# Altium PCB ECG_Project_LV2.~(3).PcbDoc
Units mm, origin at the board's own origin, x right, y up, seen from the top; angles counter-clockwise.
Board outline 76.71 x 49.78 mm, 2 copper layers (Top Layer, Bottom Layer); 26 components, 19 nets, 74 pads, 0 vias.
Unrouted connection lines stored in the file: 2.
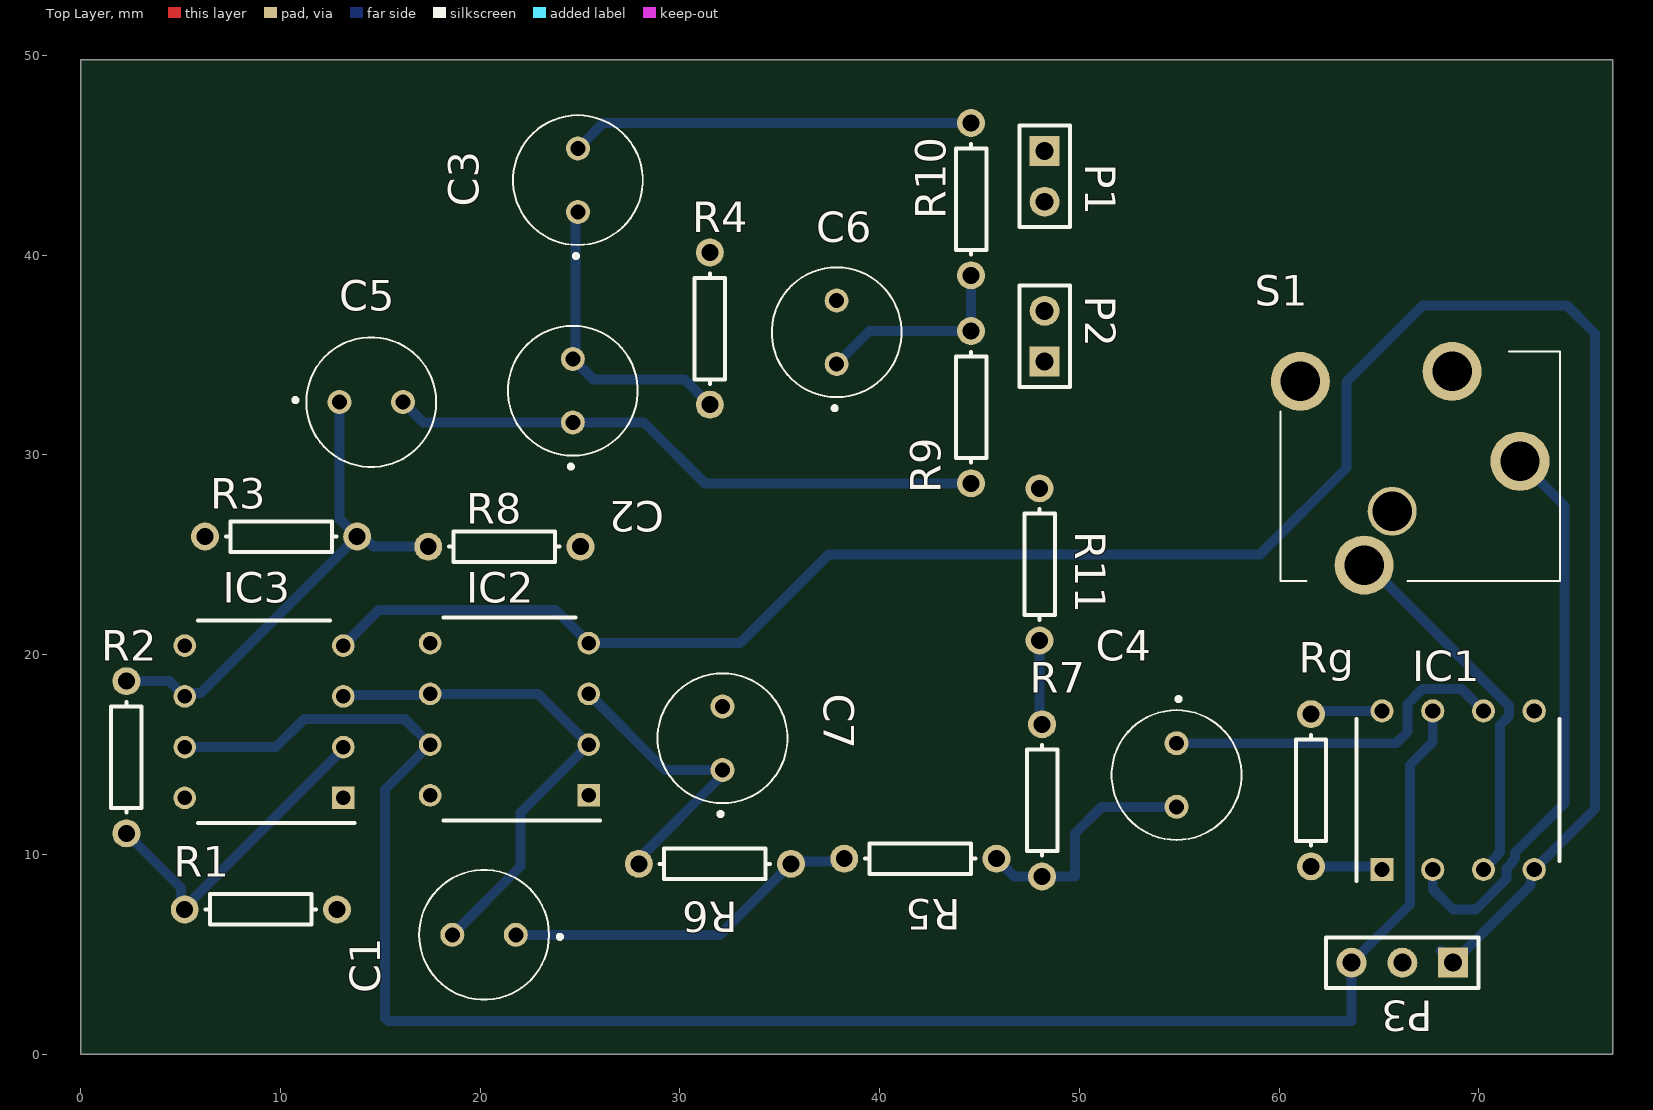
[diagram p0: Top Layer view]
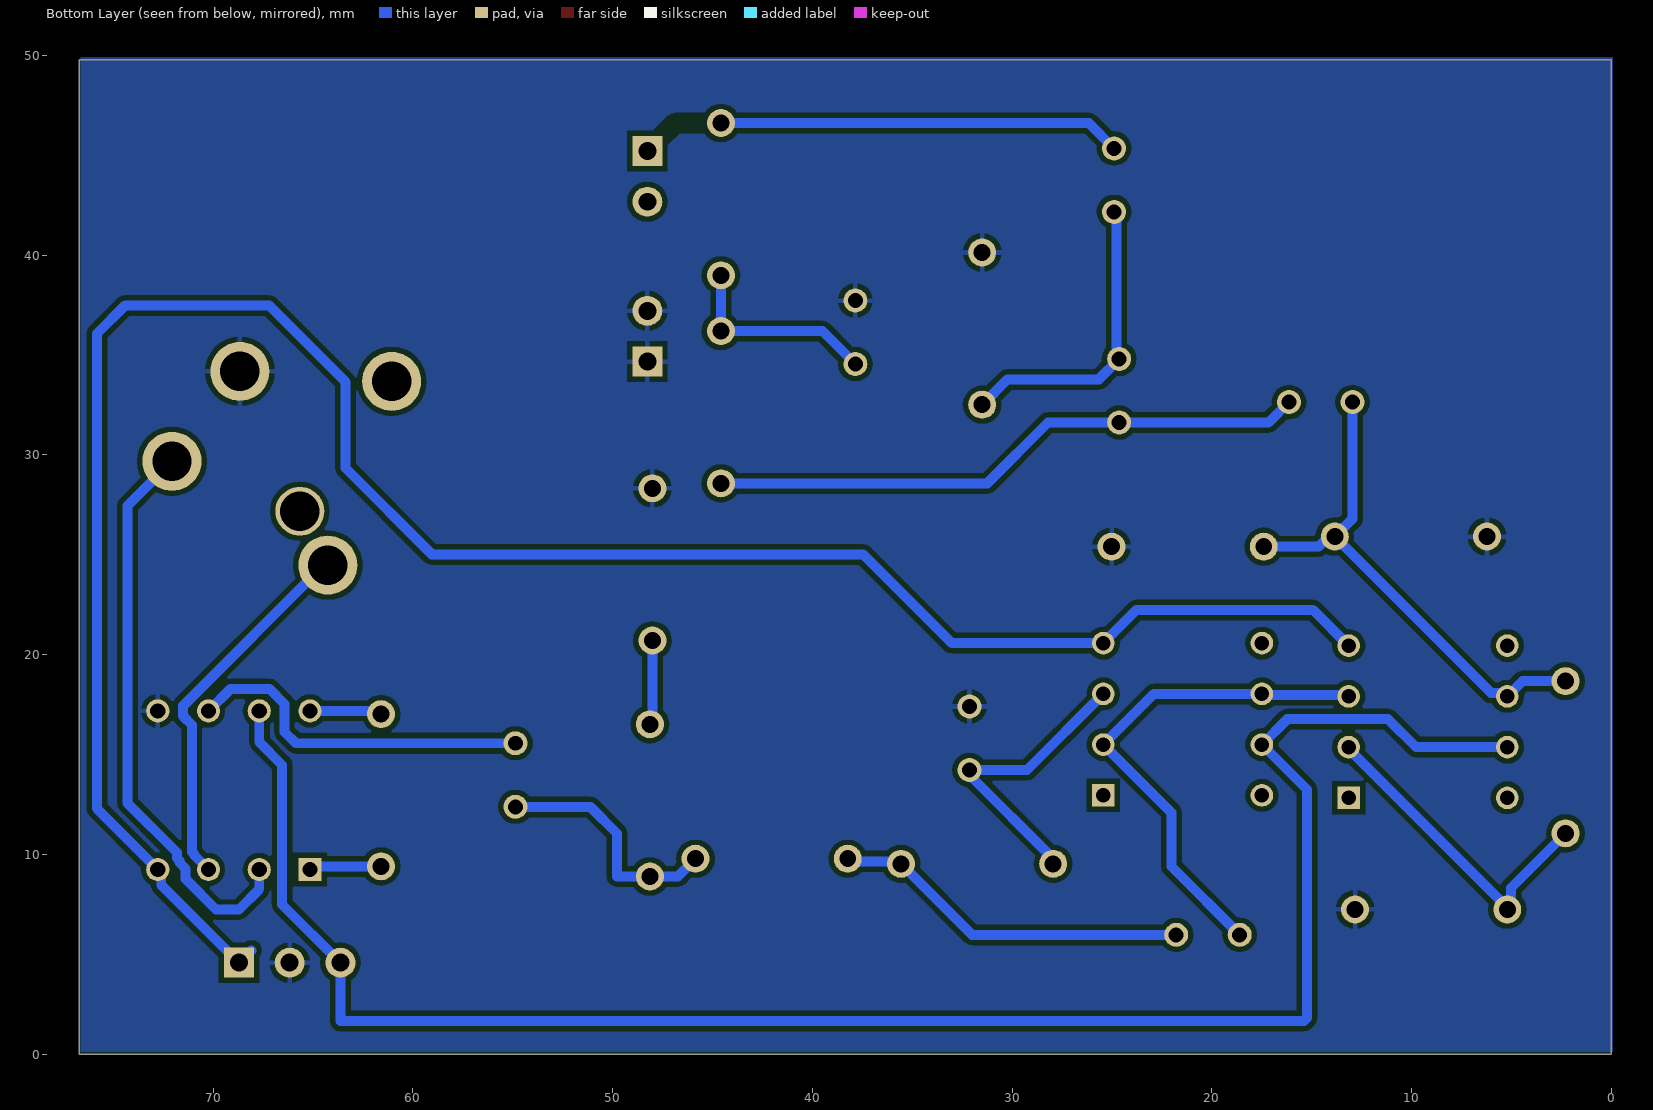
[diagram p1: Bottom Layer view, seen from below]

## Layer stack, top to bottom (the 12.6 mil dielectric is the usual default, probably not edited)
Top Solder: solder mask 0.0102, Solder Resist, Dk 3.5
Top Layer: signal copper 0.0356
Dielectric 1: dielectric 0.32, FR-4, Dk 4.8
Bottom Layer: signal copper 0.0356
Bottom Solder: solder mask 0.0102, Solder Resist, Dk 3.5

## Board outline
0,0 76.708,0 76.708,49.784 0,49.784

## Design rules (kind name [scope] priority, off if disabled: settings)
Clearance [All] p1: gap=0.254 ignorepadtopadclearanceinfootprint=FALSE except(0: Arc-Hole Track-Hole SMDPad-Hole THPad-Hole Via-Hole Fill-Hole Poly-Hole Region-Hole Text-Hole)
PolygonConnect [All] p1: connectstyle=Relief reliefconductorwidth=0.254 reliefentries=4 polygonreliefangle="90 Angle" airgapwidth=0.254
RoutingVias [All] p1: holewidth=0.711 width=1.27 viastyle="Through Hole" minholewidth=0.711 minwidth=1.27 maxholewidth=0.711 maxwidth=1.27
SolderMaskExpansion [All] p1: expansion=0.102
Width [All] p1: maxlimit=0.5 minlimit=0.5 preferedwidth=0.5
30 further rules are at their usual default settings.

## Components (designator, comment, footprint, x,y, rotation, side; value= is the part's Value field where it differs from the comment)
C1 "1uF" TAP106K016GSB 20.193,5.969 r180 top
C2 "100nF" TAP106K016GSB 24.638,33.213 r90 top
C3 "100nF" TAP106K016GSB 24.892,43.754 r90 top
C4 "10uF" TAP106K016GSB 54.864,13.97 r270 top
C5 "10uF" TAP106K016GSB 14.544,32.639 r0 top
C6 "220nF" TAP106K016GSB 37.846,36.134 r90 top
C7 "1uF" TAP106K016GSB 32.131,15.809 r90 top
IC1 "AD620AN" DIP794W56P254L959H533Q8N 68.961,13.208 r90 top
IC2 "LF411ACN_NOPB" DIP794W53P254L959H508Q8N 21.463,16.764 r180 top
IC3 "LM741CN" DIP794W53P254L959H508Q8N 9.177,16.637 r180 top
P1 "Output" HDR1X2 48.26,45.212 r270 top
P2 "OutputGround" HDR1X2 48.26,34.671 r90 top
P3 "Power" HDR1X3 68.707,4.572 r180 top
R1 "Res1" AXIAL-0.3 9.017,7.239 r0 top value=1K
R2 "Res1" AXIAL-0.3 2.286,14.859 r90 top value=56K
R3 "Res1" AXIAL-0.3 10.033,25.908 r180 top value=1.5K
R4 "Res1" AXIAL-0.3 31.496,36.322 r270 top value=15K
R5 "Res1" AXIAL-0.3 42.037,9.779 r180 top value=8.04K
R6 "Res1" AXIAL-0.3 31.75,9.525 r180 top value=8.04K
R7 "Res1" AXIAL-0.3 48.133,12.7 r270 top value=150K
R8 "Res1" AXIAL-0.3 21.209,25.4 r180 top value=2.2K
R9 "Res1" AXIAL-0.3 44.577,32.385 r90 top value=33K
R10 "Res1" AXIAL-0.3 44.577,42.799 r90 top value=33K
R11 "Res1" AXIAL-0.3 48.006,24.511 r270 top value=8.4K
Rg "Res1" AXIAL-0.3 61.595,13.208 r90 top value=560
S1 "35RAPC4BH3" 35RAPC4BH3 72.059,29.678 r180 top

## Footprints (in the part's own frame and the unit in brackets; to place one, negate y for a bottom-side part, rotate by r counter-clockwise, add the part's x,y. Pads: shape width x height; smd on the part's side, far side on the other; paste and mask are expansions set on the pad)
35RAPC4BH3 [mm]
  round 2.955 hole 1.97: 1(0,0) 2(7.8,5.2) 4(11,-4) 5(3.4,-4.5)
  round 2.447 hole 1.97: 3(6.4,2.5)
  silkscreen extent -2,-5.5 12,6
AXIAL-0.3 [mm] "Axial Device, Thru-Hole; 2 Leads; 0.3 in Pin Spacing"
  round 1.4 hole 0.85: 1(-3.81,0) 2(3.81,0)
  silkscreen extent -2.77,-0.76 2.77,0.76
DIP794W53P254L959H508Q8N [mm]
  rect 1.13x1.13 hole 0.73: 1(-3.97,3.81)
  round 1.13 hole 0.73: 2(-3.97,1.27) 3(-3.97,-1.27) 4(-3.97,-3.81) 5(3.97,-3.81) 6(3.97,-1.27) 7(3.97,1.27) 8(3.97,3.81)
  silkscreen extent -4.53,-5.08 3.3,5.08, body extent -4.1,-4.79 4.1,4.79, height 5.08
DIP794W56P254L959H533Q8N [mm]
  rect 1.16x1.16 hole 0.76: 1(-3.97,3.81)
  round 1.16 hole 0.76: 2(-3.97,1.27) 3(-3.97,-1.27) 4(-3.97,-3.81) 5(3.97,-3.81) 6(3.97,-1.27) 7(3.97,1.27) 8(3.97,3.81)
  silkscreen extent -4.55,-5.08 3.55,5.08, body extent -4.11,-4.79 4.11,4.79, height 5.33
HDR1X2 [mm] "Connector; Header; 2 Position"
  rect 1.5x1.5 hole 0.9: 1(0,0)
  round 1.5 hole 0.9: 2(2.54,0)
  silkscreen extent -1.27,-1.27 3.81,1.27
HDR1X3 [mm] "Connector; Header; 3 Position"
  rect 1.5x1.5 hole 0.9: 1(0,0)
  round 1.5 hole 0.9: 2(2.54,0) 3(5.08,0)
  silkscreen extent -1.27,-1.27 6.35,1.27
TAP106K016GSB [mm]
  round 1.2 hole 0.75: 1(-1.59,0) 2(1.59,0)
  silkscreen extent -3.9,-3.25 3.25,3.25

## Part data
C1 C2 C3 C4 C5 C6 C7: library part TAP106K016GSB, "Capacitor", Manufacturer_Name=AVX, Mouser Part Number=581-TAP106K016GSB
IC1: "Integrated Circuit", Manufacturer_Name="Analog Devices", Mouser Part Number=584-AD620AN, RS Part Number=3695803
IC2: "Integrated Circuit", Manufacturer_Name="Texas Instruments", Manufacturer_Part_Number=LF411ACN/NOPB, Mouser Part Number=926-LF411ACN/NOPB, RS Part Number=5339246P
IC3: "Integrated Circuit", Manufacturer_Name="Texas Instruments", Mouser Part Number=926-LM741CN, RS Part Number=4718749
P1 P2: library part "Header 2", "Header, 2-Pin"
P3: library part "Header 3", "Header, 3-Pin"
R1 R2 R3 R4 R5 R6 R7 R8 R9 R10 R11 Rg: "Resistor"
S1: "Switch", Manufacturer_Name=Switchcraft, Mouser Part Number=502-35RAPC4BH3, RS Part Number=8787229

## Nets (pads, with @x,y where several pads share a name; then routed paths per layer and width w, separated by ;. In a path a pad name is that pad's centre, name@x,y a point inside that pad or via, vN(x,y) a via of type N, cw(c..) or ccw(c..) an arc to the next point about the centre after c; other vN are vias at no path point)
+: C7.1 IC2.3 R6.2 | length 14.7
  Bottom Layer w0.5: IC2.3 29.248,14.219 C7.1 32.131,13.968 27.94,9.777 R6.2
+3.7: IC1.7 IC2.7 IC3.7 P3.3 | length 93.7
  Bottom Layer w0.5: IC3.7 9.779,15.367 11.176,16.764 16.223,16.764 IC2.7 15.24,13.241 15.24,1.8 15.389,1.651 63.627,1.651 P3.3 66.548,7.493 66.548,14.478 67.691,15.621 IC1.7
-3.7: IC1.4 IC2.4 IC3.4 P3.1 | length 109.5
  Bottom Layer w0.5: IC3.4 14.925,22.225 23.782,22.225 IC2.4 33.02,20.574 37.465,25.019 59.055,25.019 63.373,29.337 63.373,33.655 67.205,37.487 74.4,37.487 75.819,36.068 75.819,12.286 IC1.4 72.598,9.065 72.598,8.463 P3.1 P3.1@68.084,5.195
-IN: IC1.2 S1.1 | length 29.1
  Bottom Layer w0.5: IC1.2 67.691,8.255 68.707,7.239 69.85,7.239 71.374,8.763 71.374,9.271 71.687,9.584 71.687,9.687 71.81,9.81 71.81,10.088 74.295,12.573 74.295,27.442 S1.1 S1.1@71.81,29.429
GND: C6.2 C7.2 IC1.5 P2.1 P2.2 P3.2 R1.2 R3.2 R4.1 R8.1 R11.1 S1.5
NetC1_1: C1.1 R5.2 R6.1 | length 18
  Bottom Layer w0.5: C1.1 32.004,5.969 R6.1 35.687,9.652 38.1,9.652 R5.2
NetC1_2: C1.2 IC2.2 IC2.6 IC3.3 | length 25.7
  Bottom Layer w0.5: IC3.3 13.21,17.97 17.43,17.97 IC2.6 22.893,18.034 IC2.2 22.025,12.086 22.025,9.391 C1.2
NetC2_1: C2.1 C5.2 R9.1 | length 30.1
  Bottom Layer w0.5: C5.2 17.15,31.623 C2.1 28.194,31.623 31.242,28.575 R9.1
NetC2_2: C2.2 C3.1 R4.2 | length 15.3
  Bottom Layer w0.5: C3.1 24.765,42.037 24.765,34.93 C2.2 25.659,33.782 30.226,33.782 R4.2
NetC3_2: C3.2 P1.1 P1.2 R10.2 | length 20.2
  Bottom Layer w0.5: C3.2 26.157,46.609 R10.2
NetC4_1: C4.1 IC1.6 | length 17.8
  Bottom Layer w0.5: C4.1 65.852,15.56 66.421,16.129 66.421,17.526 67.183,18.288 69.121,18.288 IC1.6
NetC4_2: C4.2 R5.1 R7.2 | length 12.1
  Bottom Layer w0.5: R5.1 46.736,8.89 R7.2 49.784,8.89 49.784,11.049 51.115,12.38 C4.2
NetC5_1: C5.1 IC3.6 R2.2 R3.1 R8.2 | length 26.1
  Bottom Layer w0.5: R2.2 4.445,18.669 IC3.6 5.375,18.075 6.01,18.075 R3.1 ; C5.1 12.954,26.797 R3.1 ; R8.2 14.661,25.4 14.153,25.908 R3.1
NetC6_1: C6.1 R9.2 R10.1 | length 10.2
  Bottom Layer w0.5: C6.1 39.497,36.195 R9.2 R10.1
NetIC1_1: IC1.1 Rg.1 | length 3.6
  Bottom Layer w0.5: Rg.1 64.991,9.398 IC1.1
NetIC1_3: IC1.3 S1.2 | length 18.9
  Bottom Layer w0.5: S1.2 64.464,24.478 71.501,17.441 71.501,16.915 71.056,16.47 71.056,10.122 70.933,9.999 70.933,9.94 IC1.3
NetIC1_8: IC1.8 Rg.2 | length 3.6
  Bottom Layer w0.5: Rg.2 61.755,17.178 IC1.8
NetIC3_2: IC3.2 R1.1 R2.1 | length 16.4
  Bottom Layer w0.5: R2.1 5.015,8.32 5.015,7.431 R1.1 5.207,7.333 13.147,15.273 IC3.2
NetR7_1: R7.1 R11.2 | length 4.2
  Bottom Layer w0.5: R11.2 48.006,16.637 R7.1
pads on no net: IC2.1 IC2.5 IC2.8 IC3.1 IC3.5 IC3.8 S1.3 S1.4

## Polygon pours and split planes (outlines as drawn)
GND on Bottom Layer (solid, pour order 0): -0.079,0.127 -0.079,49.911 76.629,49.911 76.629,0.127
